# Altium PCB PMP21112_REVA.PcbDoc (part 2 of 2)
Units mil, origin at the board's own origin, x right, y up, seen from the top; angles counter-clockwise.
Board outline 3800 x 2750 mil, 4 copper layers (Top Layer, Signal Layer 1, Signal Layer 2, Bottom Layer), stack 68.2 mil thick; 110 components, 47 nets, 341 pads, 287 vias.
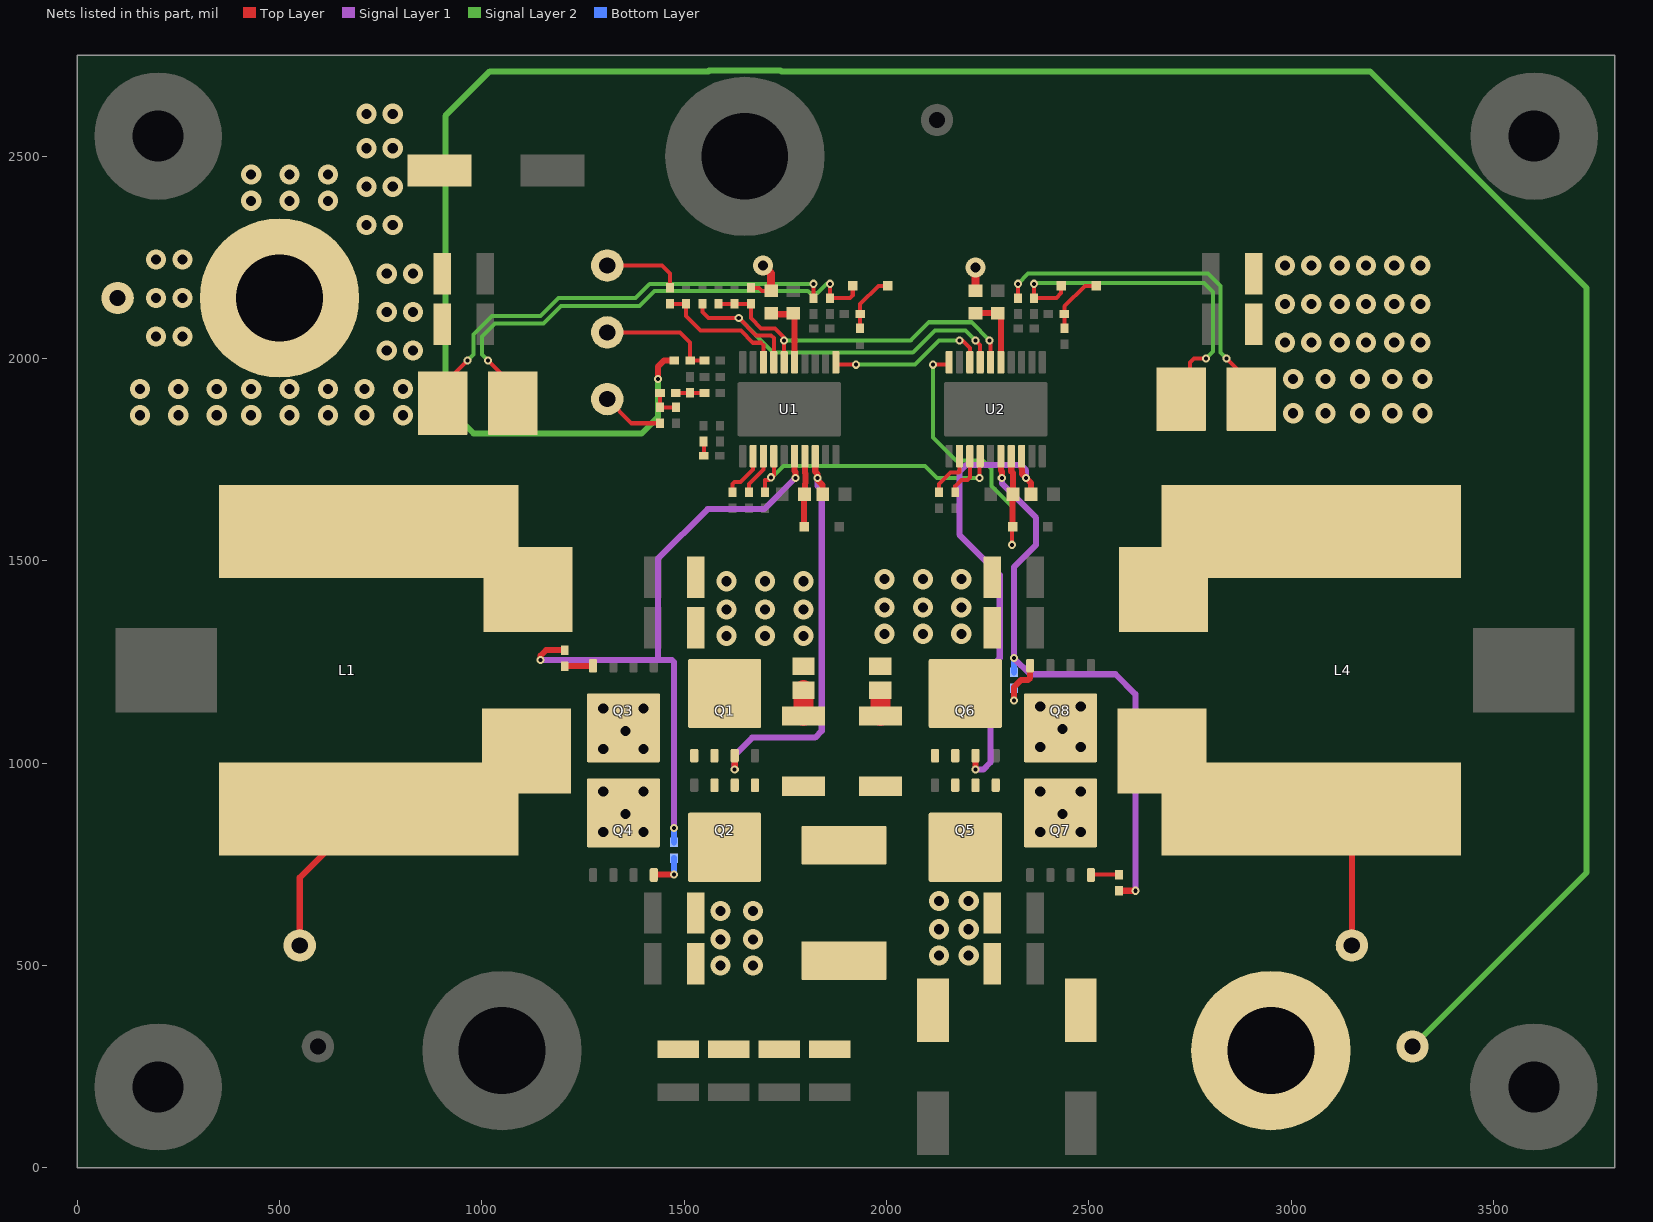
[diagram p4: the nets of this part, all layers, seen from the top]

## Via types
v1: diameter 50, hole 25, Top Layer to Bottom Layer, 205 vias
v2: diameter 20, hole 10, Top Layer to Bottom Layer, 52 vias
v3: diameter 19.68, hole 7.87, Top Layer to Bottom Layer, 18 vias
v4: diameter 19.68, hole 7.87, Top Layer to Bottom Layer, tented both sides, 12 vias

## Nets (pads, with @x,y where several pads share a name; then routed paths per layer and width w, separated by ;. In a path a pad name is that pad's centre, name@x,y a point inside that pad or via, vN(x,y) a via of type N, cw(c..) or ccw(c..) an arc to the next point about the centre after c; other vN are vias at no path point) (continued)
LO1: R8.2 R19.2 U1.16 | length 1579.5
  Top Layer w15: v2(1145,1255) 1145,1266.02 1158.66,1279.69 R8.2@1205,1279.69 ; U1.16@1772.8,1758.86 1772.8,1722.2 1775,1720 v2(1775,1705)
  Signal Layer 1 w15: v2(1145,1255) 1470,1255 1475,1250 1475,956.26 1474.63,955.88 1474.63,840.37 v2(1475,840) ; 1435,1257.5 1435,1505 1558.35,1628.35 1697.46,1628.35 1774.12,1705 v2(1775,1705)
  Bottom Layer w15: R19.2@1475,804.69 v2(1475,840)
LO2: R28.2 R32.2 U2.16 | length 1455.7
  Top Layer w15: U2.16@2282.8,1758.86 2282.8,1723.66 2285,1721.46 v2(2285,1705) ; R28.2@2575.31,685 v2(2615,685)
  Signal Layer 1 w15: v2(2285,1705) 2285,1691.57 2370,1606.57 2370,1540 2315,1485 v2(2315,1260) 2355,1220 2566.05,1220 2615,1171.05 v2(2615,685)
  Bottom Layer w15: R32.2@2315,1224.69 v2(2315,1260)
Mode1: R17.2 U1.13 | length 104.1
  Top Layer w10: R17.2@1660,1669.69 1660,1690 1696.02,1726.02 U1.13@1696.02,1758.86
Mode2: R31.2 U2.13 | length 112.9
  Top Layer w10: R31.2@2170,1669.69 2170,1685 2185,1700 2200,1700 2206.02,1706.02 U2.13@2206.02,1758.86
NetC1_1: C1.1 C4.1 C5.1 C6.1 C7.1 C24.1 C28.1 C29.1 C30.1 C31.1 L3.1 Q1.5 Q1.6 Q1.7 Q1.8 Q1.9@1600,1172.52 Q2.5 Q2.6 Q2.7 Q2.8 Q2.9@1600,792.48 Q5.5 Q5.6 Q5.7 Q5.8 Q5.9@2195,792.48 Q6.5 Q6.6 Q6.7 Q6.8 Q6.9@2195,1172.52
  other v1: 1590,500 1670,500 2130,525 2203.07,525 1590,565 1670,565 2130,590 2203.07,590 1590,635 1670,635 2130,660 2203.07,660 1605,1315 1700,1315 1795,1315 1995,1320 2090,1320 2185,1320 1605,1380 1700,1380 1795,1380 1995,1385 2090,1385 2185,1385 1605,1450 1700,1450 1795,1450 1995,1455 2090,1455 2185,1455
NetC1_2: C1.2 R1.1 | length 63.9
  Top Layer w50: R1.1@1795,1116.61 C1.2@1795,1180.47
NetC11_2: C11.2 R14.2 | length 35.4
  Top Layer w10: R14.2@1548.35,1795.31 1548.66,1795 C11.2@1548.66,1760
NetC13_1: C13.1 R10.2 U1.5 | length 177.5
  Top Layer w15: R10.2@1715,2112.44 1717.8,2109.65 1772.8,2109.65 U1.5@1772.8,1991.14
NetC16_1: C16.1 R11.2 R12.1 | length 70.6
  Top Layer w10: R12.1@1479.68,1915 R11.2@1550.31,1915
NetC17_1: C17.1 R12.2 R13.1 | length 75
  Top Layer w10: R12.2@1440,1914.69 R13.1@1440,1879.68 C17.1@1480,1879.68
NetC18_2: C18.2 Sync.1 | length 199
  Top Layer w10: Sync.1@1310,2230 1445.68,2230 1465,2210.68 C18.2@1465,2174.69
NetC24_2: C24.2 R22.1 | length 58.9
  Top Layer w50: R22.1@1985,1116.61 C24.2@1985,1175.47
NetC35_1: C35.1 R29.2 U2.5 | length 168.5
  Top Layer w15: R29.2@2220,2112.44 C35.1@2275,2112.44 ; U2.5@2282.8,1991.14 C35.1@2282.8,2104.65
NetD1_1: D1.1 L1.2 L2.2 R2.2 R4.2 | length 1232.8
  Top Layer w10: v2(1015,1995) 1076.61,1933.39 R2.2@1076.61,1890 ; v2(1860,2185) R4.2@1860,2149.69 1909.69,2149.69 1916.69,2156.69 D1.1@1916.69,2180
  Signal Layer 2 w10: v2(1015,1995) 1000,2010 1000,2054.72 1032.4,2087.13 1152.4,2087.13 1195.14,2129.86 1389.86,2129.86 1427.13,2167.13 1805.53,2167.13 1810.53,2162.13 1829.47,2162.13 1852.35,2185 v2(1860,2185)
NetD1_2: D1.2 R5.2 R6.2 | length 147.1
  Top Layer w10: R6.2@1934.69,2075 R5.2@1934.69,2110 1934.69,2134.69 1980,2180 D1.2@2003.31,2180
NetD3_1: D3.1 L4.1 L5.2 R23.2 R25.2 | length 862.3
  Top Layer w10: v2(2365,2185) R25.2@2365,2149.69 2419.69,2149.69 2431.69,2161.69 D3.1@2431.69,2180 ; R23.2@2750,1921.61 2750,1990 2760,2000 v2(2790,2000)
  Signal Layer 2 w10: v2(2365,2185) 2367.36,2187.36 2784.76,2187.36 2807.13,2165 2807.13,2017.13 v2(2790,2000)
NetD3_2: D3.2 R26.2 R27.2 | length 154
  Top Layer w10: R27.2@2440,2074.69 2440,2129.5 2490.5,2180 D3.2@2518.31,2180
NetQ3_4: Q3.4 R8.1 | length 69.3
  Top Layer w15: R8.1@1205,1240.32 Q3.4@1274.29,1240.32
NetQ4_4: Q4.4 R19.1 | length 89.3
  Top Layer w15: Q4.4@1426.02,725 v2(1475,725)
  Bottom Layer w15: v2(1475,725) R19.1@1475,765.32
NetQ7_4: Q7.4 R28.1 | length 69.3
  Top Layer w10: Q7.4@2505.71,724.68 R28.1@2575,724.68
NetQ8_4: Q8.4 R32.1 | length 143.3
  Top Layer w15: v2(2315,1155) 2315,1188.3 2332.19,1205.49 2349.84,1205.49 2355,1210.65 Q8.4@2355,1241.02
  Bottom Layer w15: v2(2315,1155) R32.1@2315,1185.32
NetR7_2: R7.2 R9.1 TP2.1 | length 295.9
  Top Layer w10: TP2.1@1310,2065 1490,2065 1514.69,2040.31 R7.2@1514.69,1995 R9.1@1550.32,1995
NetR13_2: R13.2 TP3.1 | length 154.7
  Top Layer w10: TP3.1@1310,1900 1369.69,1840.31 R13.2@1440,1840.31
RES: C15.1 U1.14 U2.14 | length 695.3
  Top Layer w10: C15.1@1700,1669.68 1700,1700 1710,1700 1721.61,1711.61 U1.14@1721.61,1758.86 ; v2(2230,1705) U2.14@2230,1757.24
  Signal Layer 2 w10: v2(1715,1706.81) 1716.81,1706.81 1745,1735 2095,1735 2125,1705 v2(2230,1705)
Slope1: R16.2 U1.12 | length 118.7
  Top Layer w10: R16.2@1620,1669.69 1620,1690 1625,1695 1639.72,1695 1670.43,1725.71 U1.12@1670.43,1758.86
Slope2: R30.2 U2.12 | length 121.8
  Top Layer w10: R30.2@2130,1669.69 2130,1690 2158.43,1718.43 2178.43,1718.43 2180.43,1720.43 U2.12@2180.43,1758.86
SS: C14.1 U1.7 U2.7 | length 995
  Top Layer w10: C14.1@1545,2135.32 1545,2115 1560,2100 v2(1635,2100) 1677.87,2057.13 1715,2057.13 1721.61,2050.51 U1.7@1721.61,1991.14 ; v2(2220,2045) 2231.61,2033.39 U2.7@2231.61,1991.14
  Signal Layer 2 w10: v2(1635,2100) 1720,2015 2065,2015 2120,2070 2195,2070 v2(2220,2045)
SW1: C8.2 L1.1 L2.1 Q1.1 Q1.2 Q1.3 Q2.1 Q2.2 Q2.3 Q3.5 Q3.6 Q3.7 Q3.8 Q3.9@1350,1087.48 Q4.5 Q4.6 Q4.7 Q4.8 Q4.9@1350,877.52 R1.2 TP1.1 U1.18 | length 1447.6
  Top Layer w15: TP1.1@550,550 550,717.48 L2.1@720,887.48 ; v2(1625,985) Q1.3@1625,1018.98 ; U1.18@1823.98,1758.86 1823.98,1720.73 1830,1714.7 v2(1830,1705) 1830,1700 1842.44,1687.56 C8.2@1842.44,1665
  Signal Layer 1 w15: v2(1625,985) 1625,1020.3 1668.31,1063.61 1823.61,1063.61 1840,1080 1840,1675.67 1830,1685.67 v2(1830,1705)
  other v1: 1300,830 1400,830 1355,875 1300,930 1400,930 1300,1035 1400,1035 1355,1080 1300,1135 1400,1135
SW2: C32.2 L4.2 L5.1 Q5.1 Q5.2 Q5.3 Q6.1 Q6.2 Q6.3 Q7.5 Q7.6 Q7.7 Q7.8 Q7.9@2430,877.52 Q8.5 Q8.6 Q8.7 Q8.8 Q8.9@2430,1087.48 R22.2 TP6.1 U2.18 | length 1381.7
  Top Layer w15: v2(2220,985) Q6.3@2220,1018.98 ; 2333.98,1728.37 U2.18@2333.98,1758.86 ; 2335.43,1725.97 2335.43,1714.57 v2(2345,1705) 2357.44,1692.56 C32.2@2357.44,1665 ; TP6.1@3150,550 L5.1@3150,787.48
  Signal Layer 1 w15: v2(2220,985) 2240,985 2257.13,1002.13 2257.13,1237.13 2280,1260 2280,1465 2180,1565 2180,1720 2197.35,1737.35 2331.63,1737.35 2345,1723.98 v2(2345,1705)
  other v1: 2380,830 2480,830 2435,875 2380,930 2480,930 2380,1040 2480,1040 2435,1085 2380,1140 2480,1140
SYNC1: C18.1 R20.2 U1.8 | length 333.2
  Top Layer w10: C18.1@1465,2135.32 R20.2@1505,2135.31 1505,2105 1540.28,2069.72 1640,2069.72 1670.47,2039.25 1690,2039.25 1696.02,2033.23 U1.8@1696.02,1991.14
SYNCOUT: U1.1 U2.8 | length 398.1
  Top Layer w10: U1.1@1881.3,1985 v2(1925,1985) ; v2(2180,2045) 2187.65,2045 2206.02,2026.63 U2.8@2206.02,1991.14 U2.8@2202.17,1995
  Signal Layer 2 w10: v2(1925,1985) 2070,1985 2130,2045 v2(2180,2045)
UVLO: C19.1 R18.1 R21.2 U1.6 U2.6 | length 875.5
  Top Layer w10: R21.2@1585,2135.31 C19.1@1625,2135.32 R18.1@1665,2135.32 1665,2100 1690,2075 1725,2075 1747.2,2052.8 v2(1747.2,2045) U1.6@1747.2,1991.14 ; U2.6@2257.2,1991.14 v2@2257.2,2042.8
  Signal Layer 2 w10: v2(1747.2,2045) 2060,2045 2105,2090 2210,2090 v2(2255,2045)
VCC1: C10.1 D2.2 U1.17 | length 175
  Top Layer w15: D2.2@1796.69,1585 C10.1@1796.69,1664.13 ; C10.1@1797.56,1665 1798.39,1665.83 1798.39,1690.51 1800.37,1692.5 1800.37,1715.51 1798.39,1717.5 U1.17@1798.39,1758.86
VCC2: C34.1 D4.2 U2.10 U2.17 | length 817
  Top Layer w10: v2(2115,1985) U2.10@2148.7,1985 ; v2(2310,1540) D4.2@2310,1583.31
  Top Layer w15: U2.17@2308.39,1758.86 2308.39,1721.61 2312.56,1717.44 C34.1@2312.56,1665 ; D4.2@2311.69,1585 C34.1@2311.69,1664.13
  Signal Layer 2 w10: v2(2115,1985) 2115,1805 2171.38,1748.62 2238.82,1748.62 2260,1727.44 2260,1685 2310,1635 v2(2310,1540)
Vin: C2.1 C3.1 C25.1 C26.1 C27.1 J1.1 R2.1 R3.2 R10.1 R18.2 R23.1 R24.2 R29.1 Vin1.1 | length 2098
  Top Layer w10: R2.1@903.39,1933.39 v2(965,1995) ; R18.2@1665,2174.69 1685.31,2174.69 1692.44,2167.56 R10.1@1715,2167.56 ; R3.2@1820,2149.69 v2(1820,2185) ; R24.2@2325,2149.69 v2(2325,2185) ; v2(2840,2000) R23.1@2901.61,1938.39
  Top Layer w20: v1(1695,2230) 1715,2210 R10.1@1715,2167.56 ; R29.1@2220,2167.56 v1(2220,2225)
  Signal Layer 2 w10: v2(965,1995) 980,2010 980,2060 1025,2105 1145,2105 1190,2150 1380,2150 1415,2185 v2(1820,2185) ; v2(2325,2185) 2350,2210 2795,2210 2825,2180 2825,2015 v2(2840,2000)
  other v1: 155,1860 250,1860 345,1860 430,1860 525,1860 620,1860 710,1860 805,1860 3005,1865 3085,1865 3170,1865 3250,1865 3325,1865 155,1925 250,1925 345,1925 430,1925 525,1925 620,1925 710,1925 805,1925 3005,1950 3085,1950 3170,1950 3250,1950 3325,1950 765,2020 830,2020 2985,2040 3050,2040 3120,2040 3185,2040 3255,2040 3320,2040 195,2055 260,2055 765,2115 830,2115 2985,2135 3050,2135 3120,2135 3185,2135 3255,2135 3320,2135 195,2150 260,2150 765,2210 830,2210 2985,2230 3050,2230 3120,2230 3185,2230 3255,2230 3320,2230 195,2245 260,2245 715,2330 780,2330 430,2390 525,2390 620,2390 715,2425 780,2425 430,2455 525,2455 620,2455 715,2520 780,2520 715,2605 780,2605
Vout: C20.1 C21.1 C22.1 C23.1 C36.1 C37.1 J2.1 L3.2 R7.1 Vout.1 | length 6599.2
  Top Layer w15: v2(1435,1950) 1435,1980 1450,1995 R7.1@1475.32,1995
  Signal Layer 2 w15: v2(1435,1950) 1435,1855 1395,1815 980,1815 910,1885 910,2600 1020,2710 1559.87,2710 1562.09,2712.22 1737.91,2712.22 1740.13,2710 3195,2710 3730,2175 3730,730 Vout.1@3300,300
pads on no net: H1.1 H2.1 H3.1 H4.1 L1.3 L4.3 Q1.9@1542.13,1122.91 Q1.9@1542.13,1189.06 Q1.9@1600,1122.91 Q1.9@1600,1189.06 Q1.9@1657.87,1122.91 Q1.9@1657.87,1189.06 Q2.9@1542.13,775.94 Q2.9@1542.13,842.09 Q2.9@1600,775.94 Q2.9@1600,842.09 Q2.9@1657.87,775.94 Q2.9@1657.87,842.09 Q3.9@1292.13,1070.94 Q3.9@1292.13,1137.09 Q3.9@1350,1070.94 Q3.9@1350,1137.09 Q3.9@1407.87,1070.94 Q3.9@1407.87,1137.09 Q4.9@1292.13,827.91 Q4.9@1292.13,894.06 Q4.9@1350,827.91 Q4.9@1350,894.06 Q4.9@1407.87,827.91 Q4.9@1407.87,894.06 Q5.9@2137.13,775.94 Q5.9@2137.13,842.09 Q5.9@2195,775.94 Q5.9@2195,842.09 Q5.9@2252.87,775.94 Q5.9@2252.87,842.09 Q6.9@2137.13,1122.91 Q6.9@2137.13,1189.06 Q6.9@2195,1122.91 Q6.9@2195,1189.06 Q6.9@2252.87,1122.91 Q6.9@2252.87,1189.06 Q7.9@2372.13,827.91 Q7.9@2372.13,894.06 Q7.9@2430,827.91 Q7.9@2430,894.06 Q7.9@2487.87,827.91 Q7.9@2487.87,894.06 Q8.9@2372.13,1070.94 Q8.9@2372.13,1137.09 Q8.9@2430,1070.94 Q8.9@2430,1137.09 Q8.9@2487.87,1070.94 Q8.9@2487.87,1137.09 U1.21@1760,1875 U2.1 U2.21@2270,1875

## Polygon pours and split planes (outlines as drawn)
Vout on Top Layer "Vout" (solid, remove dead copper, pour order 18): 1425,350 1425,245 2700,245 2700,0 3400,0 3400,500 2430,500 2430,452.32 2395,417.32 2200,417.32 2200,475 2075,475 2075,620 1715,620 1715,350
GND on Top Layer "GND" (solid, remove dead copper, pour order 28): 0,2750 0,0 3800,0 3800,2750
Vin on Top Layer "Vin" (solid, remove dead copper, pour order 0): 0,2750 0,1800 980,1800 980,1970 976.87,1970 955,1991.87 955,2255 985,2255 1035,2305 1035,2750
NetD1_1 on Top Layer "D1_1" (solid, remove dead copper, pour order 2): 345,1700 345,1455 1010,1455 1010,1320 1230,1320 1230,1540 1230,1970 1010,1970 1010,1700
SW1 on Top Layer "SW1" (solid, remove dead copper, pour order 4): 345,1005 345,920 1235.37,920 1235.37,775.39 1445,775.39 1445,920 1860,920 1860,1055 1465,1055 1465,1190 995,1190 995,1005
NetC1_1 on Top Layer "C1_1" (solid, remove dead copper, pour order 6): 1510,890 1510,435 1705,435 1705,650 2100,650 2100,435 2305,435 2305,890
NetC1_1 on Top Layer "C1_2" (solid, remove dead copper, pour order 10): 1490,1525 1490,1080 1720,1080 1720,1230 2075,1230 2075,1060 2291.47,1060 2286.47,1525
NetD3_1 on Top Layer "D3_1" (solid, remove dead copper, pour order 12): 3425,1700 2800,1700 2800,1980 2660,1980 2660,1550 2575,1550 2575,1320 2800,1320 2800,1450 3420,1450
SW2 on Top Layer "SW2" (solid, remove dead copper, pour order 16): 3420,770 3420,1005 2795,1005 2790,1010 2790,1135 2570,1135 2570,1180 2320,1180 2320,1040 1920,1040 1920,920 2320,920 2320,770 2550,770 2550,900 2680,900 2680,770
GND on Bottom Layer "GND" (solid, remove dead copper, pour order 34): 0,1975 0,-5 5,0 3805,0 3805,1975
Vin on Bottom Layer "Vin" (solid, remove dead copper, pour order 26): 0,2750 0,1795 1510,1795 1510,1970 2480,1970 2480,1795 3800,1795 3800,2750
NetC1_1 on Bottom Layer "C1" (solid, remove dead copper, pour order 22): 1505.57,1510 1505.57,435 2305,435 2305,1510
GND on Signal Layer 1 "GND" (solid, remove dead copper, pour order 30): 0,2750 0,0 3800,0 3800,2750
GND on Signal Layer 2 "GND" (solid, remove dead copper, pour order 32): 0,2750 -5,2745 -5,0 3800,0 3800,2750

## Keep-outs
Keep-Out Layer:
  text ".Layer_Name" at 577,-858.49 h60

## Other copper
Top Layer:
  rectangle net Vin: 2865,1815 3405,2295
  pour cut-out: 930,1965 985,1965 985,2010 930,2010
  text ".Layer_Name" at 577,-858.49 h60
Signal Layer 1:
  rectangle net SW2: 2340,775 2530.39,1180
  rectangle net SW1: 1260,780 1440,1180
  pour cut-out: 155,2385 155,1900 820,1900 820,2385
Signal Layer 2:
  rectangle net SW1: 1260,775 1440,1180
  rectangle net SW2: 2340,775 2530,1180
  pour cut-out: 160,2385 160,1900 820,1900 820,2385
Bottom Layer:
  rectangle net SW1: 1260,785 1435,1175
  rectangle net SW2: 2335,775 2525,1180
  pour cut-out: 1435,2750 1435,2265 1850,2265 1850,2750
  text ".Layer_Name" at 577,-858.49 h60

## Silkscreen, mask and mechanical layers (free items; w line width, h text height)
Top Overlay:
  region: 2905,2465 2605,2465 2605,2385 2905,2385
  text "'.PRJ_Number'.PCB_Rev-" at 2035,2390 h108.27
  text ".Layer_Name" at 577,-858.49 h60
Bottom Overlay:
  text ".Layer_Name" at 577,-858.49 h60
Top Paste:
  text ".Layer_Name" at 577,-858.49 h60
Bottom Paste:
  text ".Layer_Name" at 577,-858.49 h60
Top Solder:
  text ".Layer_Name" at 577,-858.49 h60
  text ".Layer_Name" at 577,-858.49 h60
Bottom Solder:
  text ".Layer_Name" at 577,-858.49 h60
Drill Guide:
  text ".Layer_Name" at 577,-858.49 h60
M1 Board Outline:
  the board outline again, w10
  text ".Layer_Name" at 577,-858.49 h60
M2 Board Dimensions:
  rectangle: 0,-275 125,-150
  rectangle: 125,-400 500,-275
  lines w7: 0,-275 1000,-275 ; 125,-400 125,-150 ; 250,-400 250,-150 ; 500,-400 500,-150 ; 750,-400 750,-150 ; 0,-400 1000,-400 1000,-150 0,-150 0,-400
  text ".Layer_Name" at 577,-858.49 h60
M3 3D STEP Top:
  text ".Layer_Name" at 577,-858.49 h60
M4 3D STEP Bottom:
  text ".Layer_Name" at 577,-858.49 h60
M5 Assembly Top:
  lines w10: -292,-930.17 6308,-930.17 ; -292,-726.83 6310,-726.83 ; -292,-523.5 -292,-1133.5 3713,-1133.5 6310,-1133.5 6310,-523.5 -291.5,-523.5 -291.5,-1133.5 1284,-1133.5 ; 2173,-1133.5 2173,-523.5 ; 3440,-726.83 3440,-523.5 ; 4280,-726.83 4280,-523.5 ; 4902,-1140 4902,-937.17
  text "COMPONENTS MARKED 'DNP' SHOULD NOT BE POPULATED." at 1153.5,-318.5 h60
  text "ASSEMBLY VARIANT:" at 1153,-434 h60
  text ".VariantName" at 2189,-434 h60
  text "PCB VIEWED FROM TOP SIDE" at -228.5,-655.67 h60
  text "BOARD #:" at 2248,-655.67 h60
  text ".PRJ_Number" at 2793.5,-655.67 h60
  text "REV:" at 3638,-655.67 h60
  text ".PCB_Rev" at 3929.5,-655.67 h60
  text "SVN REV:" at 4476,-655.67 h60
  text ".VersionControl_RevNumber" at 4982,-655.67 h60
  text "TID #:" at 2248,-859 h60
  text ".TID" at 2793.5,-859 h60
  text "PLOT NAME =" at -228.5,-1064.34 h60
  text ".plot_File_Name" at 577,-1064.34 h60
  text "GENERATED    :" at 2250,-1064.34 h60
  text ".Print_Date" at 3119.5,-1064.34 h60
  text ".Print_Time" at 3848.5,-1064.34 h60
  text "TEXAS INSTRUMENTS" at 5113,-1064.34 h60
M6 Assembly Bottom:
  lines w10: -292.5,-727.33 6309.5,-727.33 ; -290.5,-930.67 6309.5,-930.67 ; 1115.5,-1140.5 1115.5,-937.67 ; 1737.5,-727.33 1737.5,-524 ; 2577.5,-727.33 2577.5,-524 ; 3844.5,-1134 3844.5,-524 ; 4733.5,-1134 6309,-1134 6309,-524 -292.5,-524 -292.5,-1134 2304.5,-1134 6309.5,-1134 6309.5,-524
  text "COMPONENTS MARKED 'DNP' SHOULD NOT BE POPULATED." at 6102,-318 h60
  text ".VariantName" at 5058,-434 h60
  text "ASSEMBLY VARIANT:" at 6097,-434 h60
  text ".VersionControl_RevNumber" at 1035.5,-656.17 h60
  text "SVN REV:" at 1541.5,-656.17 h60
  text ".PCB_Rev" at 2088,-656.17 h60
  text "REV:" at 2379.5,-656.17 h60
  text ".PRJ_Number" at 3224,-656.17 h60
  text "BOARD #:" at 3769.5,-656.17 h60
  text "PCB VIEWED FROM BOTTOM SIDE" at 6246,-656.17 h60
  text ".TID" at 3224,-859.5 h60
  text "TID #:" at 3769.5,-859.5 h60
  text "TEXAS INSTRUMENTS" at 904.5,-1064.84 h60
  text ".Print_Time" at 2169,-1064.84 h60
  text ".Print_Date" at 2898,-1064.84 h60
  text "GENERATED    :" at 3767.5,-1064.84 h60
  text ".plot_File_Name" at 5440.5,-1064.84 h60
  text "PLOT NAME =" at 6246,-1064.84 h60
M9 Title Sheet:
  drawing of 57 lines, arcs and shapes, not listed
  text "1" at 739.84,8036.5 h70
  text "2" at 3235.5,8036.5 h70
  text "3" at 5724.84,8036.5 h70
  text "4" at 8231.51,8036.5 h70
  text "5" at 10730.5,8036.5 h70
  text "6" at 13235.5,8036.5 h70
  text "A" at -416.5,6893.5 h70
  text "A" at 14383.5,6893.5 h70
  text "B" at -416.5,4513.5 h70
  text "B" at 14383.5,4513.5 h70
  text "C" at -416.5,2138.5 h70
  text "C" at 14383.5,2138.5 h70
  text "PROJECT TITLE:" at 11343.5,277.5 h45
  text ".PRJ_Title" at 11393.5,144.17 h70
  text "DESIGNED FOR:" at 11343.5,-23.5 h45
  text ".PRJ_Customer" at 11393.5,-163.5 h70
  text "D" at -416.5,-231.5 h70
  text "D" at 14383.5,-231.5 h70
  text "FILE NAME:" at 11343.5,-323.5 h45
  text ".PCB_File_Name_No_Path" at 11393.5,-443.5 h70
  text "Texas Instruments (TI) and/or its licensors do not warrant the accuracy or completeness of this specification" at 6374,-605.34 h45
  text "ENGINEER:" at 11343.5,-613.5 h45
  text "LAYOUT BY:" at 12848.5,-613.5 h45
  text "or any information contained therein. TI and/or its licensors do not warrant that this design will meet" at 6329.01,-718 h45
  text ".PRJ_Engineer" at 11393.5,-768.49 h70
  text ".PCB_Layout" at 12899,-768.49 h70
  text "the specifications, will be suitable for your application or fit for any particular purpose, or will operate in" at 6329.01,-830.67 h45
  text ".Layer_Name" at 577,-858.49 h60
  text "ALTIUM DESIGNER VERSION:" at 12848.5,-923.5 h45
  text "an implementation. TI and/or its licensors do not warrant that the design is production worthy. You should" at 6329.01,-943.33 h45
  text "completely validate and test your design implementation to confirm the system functionality for your application." at 6374,-1056 h45
  text ".print_Scale" at 11393.5,-1056.83 h70
  text ".Application_BuildNumber" at 12899,-1056.83 h70
  text "1" at 739.84,-1263.5 h70
  text "2" at 3235.5,-1263.5 h70
  text "3" at 5724.84,-1263.5 h70
  text "4" at 8231.51,-1263.5 h70
  text "5" at 10730.5,-1263.5 h70
  text "6" at 13235.5,-1263.5 h70
M10 Fab Notes:
  drawing of 189 lines, arcs and shapes, not listed
  text "DESIGN INFORMATION" at 12382.02,6356.17 h60
  text "MIN. TRACK WIDTH:" at 11737.46,6224.05 h60
  text "8" at 12833.7,6224.05 h60
  text "MIL" at 12988.46,6224.05 h60
  text "MIN. CLEARANCE:" at 11737.46,6099.92 h60
  text "0.2" at 12773.7,6099.93 h60
  text "mm" at 12988.46,6099.92 h60
  text "MIN. VIA PAD SIZE:" at 11737.46,5975.8 h60
  text "24" at 12803.71,5975.8 h60
  text "MIL" at 12988.46,5975.8 h60
  text "0.05mm (2MIL)" at 12432.46,5845.9 h60
  text "MINIMUM ANNULAR RING" at 11408.23,5837.67 h60
  text "EXTERNAL" at 13140.46,5837.67 h60
  text "PER" at 11608.23,5727.55 h60
  text "IPC-D-275 CLASS 2 LEVEL C" at 11828.23,5727.54 h60
  text "MIL, HOLES" at 13316.46,5627.07 h60
  text "+/-" at 12924,5618.48 h60
  text "+/-" at 13778,5618.48 h60
  text "REGISTRATION TOLERANCES:" at 11408.23,5617.42 h60
  text "METAL" at 12608,5617.42 h60
  text "5" at 13184.2,5617.42 h60
  text "3" at 14017.2,5617.42 h60
  text "MIL" at 14133.46,5617.42 h60
  text "HOLE SIZE TOLERANCE (UNLESS OTHERWISE SPECIFIED):" at 11408.23,5519.1 h60
  text "+/-" at 13778,5516.23 h60
  text "3" at 14017.2,5515.17 h60
  text "MIL" at 14133.46,5515.17 h60
  text "MATERIAL:" at 11333.46,5377.52 h60
  text "FR-4 High Tg" at 12319.9,5249 h60
  text "X" at 12175.46,5241.01 h60
  text "FR-408" at 11754.46,5236.49 h60
  text "OTHER" at 13242.46,5236.49 h60
  text "62 MIL (1.6mm) +/-10%" at 12074.56,5093.46 h60
  text "X" at 11954.46,5091.01 h60
  text "THICKNESS:" at 11408.23,5085.24 h60
  text "OTHER" at 13359.46,5085.24 h60
  text "TOLERANCE:" at 11408.23,4946.92 h60
  text "X" at 12256.46,4946.92 h60
  text "ANSI IPC-6012 TYPE 3 CLASS 2" at 12434.48,4946.92 h60
  text "OTHER +/-" at 12434.46,4802.73 h60
  text "BOW & TWIST:" at 11408.23,4657.54 h60
  text "X" at 12256.46,4657.54 h60
  text "ANSI IPC-6012 TYPE 3 CLASS 2" at 12434.48,4657.54 h60
  text "OTHER +/-" at 12434.46,4510.85 h60
  text "DRILLING:" at 11333.46,4380.23 h60
  text "NC_DRILL FILES" at 13094.46,4275.04 h60
  text "REFERENCE:" at 11408.23,4271.1 h60
  text "X" at 12065.46,4271.01 h60
  text "AS SHOWN" at 12243.46,4271.1 h60
  text "X" at 12966.46,4271.1 h60
  text "OTHER" at 13392.46,4128.85 h60
  text "PTH COPPER THICKNESS:" at 11407.91,4125.32 h60
  text "X" at 12547.14,4125.32 h60
  text "20-30 um" at 12675.14,4125.32 h60
  text "BOARD FINISH:" at 11333.46,3977.73 h60
  text "SILKSCREEN:" at 11488.68,3867.6 h60
  text "X" at 12446.46,3867.6 h60
  text "TOP" at 12563.46,3867.6 h60
  text "X" at 12956.46,3867.6 h60
  text "BOTTOM" at 13074.46,3867.6 h60
  text "SILKSCREEN COLOR:" at 11488.68,3712.41 h60
  text "X" at 12445.46,3712.41 h60
  text "WHITE" at 12563.46,3712.41 h60
  text "OTHER" at 13074.46,3712.41 h60
  text "X" at 12576.46,3568.96 h60
  text "GREEN" at 12694.46,3568.96 h60
  text "OTHER" at 13312.46,3568.96 h60
  text "SOLDER RESIST COLOR:" at 11488.68,3562.1 h60
  text "X" at 12576.46,3414.71 h60
  text "MATTE" at 12694.46,3414.71 h60
  text "SEMI-GLOSS" at 13312,3414.07 h60
  text "IMMERSION GOLD (ENIG)" at 12394.46,3241.94 h60
  text "ENEPIG" at 13732,3234.72 h60
  text "SURFACE FINISH:" at 11333.46,3233.72 h60
  text "X" at 12216.46,3233.72 h60
  text "IMM. TIN/SILVER OR EQUIV" at 11663,3096.4 h60
  text "OTHER" at 13094.46,3092.47 h60
  text "ARRAY/PANEL:" at 11333.46,2937.09 h60
  text "CUT AND TRIM PER M1 BOARD OUTLINE" at 12394.46,2928.87 h60
  text "N.C. ROUTE" at 12394.46,2792.9 h60
  text "X" at 13082.46,2792.9 h60
  text "V. SCORE" at 13260.46,2792.9 h60
  text "CERTIFICATION:" at 11333.46,2663.77 h60
  text "MATERIALS AND WORKMANSHIP FOR ALL PCBS" at 12058.46,2663.77 h60
  text "TO MEET OR EXCEED THE REQUIREMENTS OF:" at 12058.46,2569.71 h60
  text "X" at 11695.97,2441.08 h60
  text "ANSI IPC-A-600F CLASS ->" at 11823.96,2441.08 h60
  text "X" at 13471.97,2441.08 h60
  text "2" at 13581.96,2441.08 h60
  text "1" at 13266.96,2439.58 h60
  text "3" at 13935.96,2439.58 h60
  text "X" at 12507.97,2293.39 h60
  text "RoHS" at 12635.96,2293.39 h60
  text "OTHER" at 13280.36,2293.39 h60
  text "PER ORDER" at 13677.42,2293.39 h60
  text "ALL BOARDS MUST MEET OR EXCEED UL94-V0 REQUIREMENTS." at 11361,2139.57 h60
  text "PCB MUST BEAR THE UL94V-0 UL REGISTERED MATERIAL ID NUMBER" at 11361,2023.5 h60
  text "ADDITIONAL REQUIREMENTS:" at 11333.46,1854.08 h60
  text "MICROSECTION:" at 11408.23,1746.95 h60
  text "YES" at 12313.96,1746.95 h60
  text "REQUIRED" at 13175.46,1602.62 h60
  text "BARE BOARD ELEC. TEST:" at 11408.23,1599.76 h60
  text "NONE" at 12713.96,1599.76 h60
  text "X" at 13057.46,1599.76 h60
  text "PER ORDER" at 13767.46,1599.76 h60
  text "XX MIL VIAS REQUIRE NON-CONDUCTIVE FILL AND PLANARIZE" at 11576.38,1394.82 h59
  text "XX MIL VIAS REQUIRE CONDUCTIVE FILL AND PLANARIZE" at 11584.38,1290.84 h60
  text "OUTER XX MIL VIAS REQUIRE 50 OHM SINGLE-ENDED IMPEDANCE" at 11583.39,1127.46 h58
  text "LAYER 2 & 3 (INNER LAYERS) XX MIL WIDE, XX MIL SPACE / TRACES REQUIRE 100 OHM DIFFERENTIAL IMPEDANCE" at 11575.39,891.74 h60
  text ".Layer_Name" at 577,-858.49 h60
M11 Gerber Information:
  lines w10: -292,-930.17 6308,-930.17 ; -292,-726.83 6310,-726.83 ; -292,-523.5 -292,-1133.5 3713,-1133.5 6310,-1133.5 6310,-523.5 -291.5,-523.5 -291.5,-1133.5 1284,-1133.5 ; 2173,-1133.5 2173,-523.5 ; 3440,-726.83 3440,-523.5 ; 4280,-726.83 4280,-523.5 ; 4902,-1140 4902,-937.17
  text "ALL ARTWORK VIEWED FROM TOP SIDE" at -228.5,-655.67 h60
  text "BOARD #:" at 2248,-655.67 h60
  text ".PRJ_Number" at 2793.5,-655.67 h60
  text "REV:" at 3638,-655.67 h60
  text ".PCB_Rev" at 3929.5,-655.67 h60
  text "SVN REV:" at 4476,-655.67 h60
  text ".VersionControl_RevNumber" at 4982,-655.67 h60
  text "LAYER NAME =" at -228.5,-858.49 h60
  text "TID #:" at 2248,-859 h60
  text ".TID" at 2793.5,-859 h60
  text "PLOT NAME =" at -228.5,-1064.34 h60
  text ".plot_File_Name" at 577,-1064.34 h60
  text "GENERATED    :" at 2250,-1064.34 h60
  text ".Print_Date" at 3119.5,-1064.34 h60
  text ".Print_Time" at 3848.5,-1064.34 h60
  text "TEXAS INSTRUMENTS" at 5113,-1064.34 h60
M12 Stackup:
  drawing of 429 lines, arcs and shapes, not listed
  text "Layer" at 218.76,7714.46 h60
  text "Name" at 628.67,7714.46 h60
  text "Material" at 1568.42,7714.46 h60
  text "Thickness" at 2428.18,7714.46 h60
  text "Constant" at 3078.02,7714.46 h60
  text "Board Layer Stack" at 3647.88,7714.46 h60
  text "1" at 218.76,7594.46 h60
  text "Top Overlay" at 628.67,7594.46 h60
  text "2" at 218.76,7474.46 h60
  text "Top Solder" at 628.67,7474.46 h60
  text "Solder Resist" at 1568.42,7474.46 h60
  text "0.40mil" at 2428.18,7474.46 h60
  text "3.5" at 3078.02,7474.46 h60
  text "3" at 218.76,7354.46 h60
  text "Top Layer" at 628.67,7354.46 h60
  text "Copper" at 1568.42,7354.46 h60
  text "2.80mil" at 2428.18,7354.46 h60
  text "4" at 218.76,7234.46 h60
  text "Dielectric1" at 628.67,7234.46 h60
  text "FR-4" at 1568.42,7234.46 h60
  text "20.00mil" at 2428.18,7234.46 h60
  text "4.8" at 3078.02,7234.46 h60
  text "5" at 218.76,7114.46 h60
  text "Signal Layer 1" at 628.67,7114.46 h60
  text "Copper" at 1568.42,7114.46 h60
  text "2.80mil" at 2428.18,7114.46 h60
  text "6" at 218.76,6994.46 h60
  text "Dielectric 2" at 628.67,6994.46 h60
  text "17.00mil" at 2428.18,6994.46 h60
  text "4.2" at 3078.02,6994.46 h60
  text "7" at 218.76,6874.46 h60
  text "Signal Layer 2" at 628.67,6874.46 h60
  text "Copper" at 1568.42,6874.46 h60
  text "2.80mil" at 2428.18,6874.46 h60
  text "8" at 218.76,6754.46 h60
  text "Dielectric 3" at 628.67,6754.46 h60
  text "FR-4" at 1568.42,6754.46 h60
  text "20.00mil" at 2428.18,6754.46 h60
  text "4.2" at 3078.02,6754.46 h60
  text "9" at 218.76,6634.46 h60
  text "Bottom Layer" at 628.67,6634.46 h60
  text "Copper" at 1568.42,6634.46 h60
  text "2.80mil" at 2428.18,6634.46 h60
  text "10" at 218.76,6514.46 h60
  text "Bottom Solder" at 628.67,6514.46 h60
  text "Solder Resist" at 1568.42,6514.46 h60
  text "0.40mil" at 2428.18,6514.46 h60
  text "3.5" at 3078.02,6514.46 h60
  text "11" at 218.76,6394.46 h60
  text "Bottom Overlay" at 628.67,6394.46 h60
  text ".Layer_Name" at 577,-858.49 h60
M13 Component Bodies Top:
  text ".Layer_Name" at 577,-858.49 h60
M14 Component Bodies Bottom:
  text ".Layer_Name" at 577,-858.49 h60
M15 Courtyards Top:
  text ".Layer_Name" at 577,-858.49 h60
M16 Courtyards Bottom:
  text ".Layer_Name" at 577,-858.49 h60
Drill Drawing:
  circle w10: c5363.8,2768.24 r27.66
  lines w10: 5336.14,2671.44 5391.46,2671.44 5363.8,2616.13 5336.14,2671.44 ; 5336.14,2865.04 5391.46,2865.04 5391.46,2920.36 5336.14,2920.36 5336.14,2865.04 ; 5336.14,3003.33 5349.97,3003.33 5349.97,2989.5 5377.63,2989.5 5377.63,3003.33 5391.46,3003.33 5391.46,3030.99 5377.63,3030.99 5377.63,3044.82 5349.97,3044.82 5349.97,3030.99 5336.14,3030.99 5336.14,3003.33 ; 5336.14,3113.96 5363.8,3127.79 5391.46,3113.96 5377.63,3141.62 5391.46,3169.28 5363.8,3155.45 5336.14,3169.28 5349.97,3141.62 5336.14,3113.96 ; 5336.14,3252.25 5349.97,3252.25 5363.8,3238.42 5377.63,3252.25 5391.46,3252.25 5377.63,3266.08 5391.46,3279.91 5377.63,3279.91 5363.8,3293.74 5349.97,3279.91 5336.14,3279.91 5349.97,3266.08 5336.14,3252.25
  lines w12: 5286,2578.79 8518.76,2578.79 ; 5286,3325.54 8518.76,3325.54 ; 5624.17,2454.33 5624.17,3450 ; 5956.28,2454.33 5956.28,3450 ; 6593.29,2454.33 6593.29,3450 ; 6852.64,2454.33 6852.64,3450 ; 7228.06,2454.33 7228.06,3450 ; 7951.91,2454.33 7951.91,3450 ; 5286,2454.33 8518.76,2454.33 8518.76,3450 5286,3450 5286,2454.33
  text "Symbol" at 5360.68,3362.88 h72
  text "Quantity" at 5661.51,3362.88 h72
  text "Finished Hole Size" at 5993.62,3362.88 h72
  text "Plated" at 6630.62,3362.88 h72
  text "Hole Type" at 6889.98,3362.88 h72
  text "Drill Layer Pair" at 7265.4,3362.88 h72
  text "Hole Tolerance" at 7989.25,3362.88 h72
  text "30" at 5661.51,3238.42 h60
  text "7.87mil (0.200mm)" at 5993.62,3238.42 h60
  text "PTH" at 6630.62,3238.42 h60
  text "Round" at 6889.98,3238.42 h60
  text "Top Layer - Bottom Layer" at 7265.4,3238.42 h60
  text "52" at 5661.51,3113.96 h60
  text "10.00mil (0.254mm)" at 5993.62,3113.96 h60
  text "PTH" at 6630.62,3113.96 h60
  text "Round" at 6889.98,3113.96 h60
  text "Top Layer - Bottom Layer" at 7265.4,3113.96 h60
  text "205" at 5661.51,2989.5 h60
  text "25.00mil (0.635mm)" at 5993.62,2989.5 h60
  text "PTH" at 6630.62,2989.5 h60
  text "Round" at 6889.98,2989.5 h60
  text "Top Layer - Bottom Layer" at 7265.4,2989.5 h60
  text "9" at 5661.51,2865.04 h60
  text "40.00mil (1.016mm)" at 5993.62,2865.04 h60
  text "PTH" at 6630.62,2865.04 h60
  text "Round" at 6889.98,2865.04 h60
  text "Top Layer - Bottom Layer" at 7265.4,2865.04 h60
  text "4" at 5661.51,2740.59 h60
  text "125.98mil (3.200mm)" at 5993.62,2740.59 h60
  text "PTH" at 6630.62,2740.59 h60
  text "Round" at 6889.98,2740.59 h60
  text "Top Layer - Bottom Layer" at 7265.4,2740.59 h60
  text "4" at 5661.51,2616.13 h60
  text "214.57mil (5.450mm)" at 5993.62,2616.13 h60
  text "PTH" at 6630.62,2616.13 h60
  text "Round" at 6889.98,2616.13 h60
  text "Top Layer - Bottom Layer" at 7265.4,2616.13 h60
  text "304 Total" at 5661.51,2491.67 h60
  text ".Layer_Name" at 577,-858.49 h60
M17 Embedded Cavity:
  text ".Layer_Name" at 577,-858.49 h60
M18 Embedded Assembly:
  text ".Layer_Name" at 577,-858.49 h60
M19 Embedded Keepout:
  text ".Layer_Name" at 577,-858.49 h60

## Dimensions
0,-400 to 1000,-400 on M2 Board Dimensions
0,0 to 0,2750 on M2 Board Dimensions
0,0 to 3800,0 on M2 Board Dimensions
